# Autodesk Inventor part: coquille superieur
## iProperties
Created: 2002-04
Part Number: coquille superieur
Material: Par défaut
Document SubType Name: Modélisation
Designer: thchene
Control State: 0
Master: False
Checked Out: False
Shininess: 20.0
Angle Display Precision: 2
Document Length Units: 11269
Document Angle Units: 11279
Document Time Units: 11290
Document Mass Units: 11283
Document Length Units Precision: 3
Document Angle Units Precision: 2
Compacted: True
Density: 0.0
Volumn: 0.0
Area: 0.0
PropertySet Name: Model Information
Author: thchene
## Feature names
1. Révolution1 [Revolution]
2. Extrusion6
3. Extrusion3
4. Extrusion4
5. trou avant [Extrusion]
6. Congé1 [Fillet]
7. Perçage trous lame 3 [Hole]
8. Extrusion19
9. Ergot centrage [Extrusion]
10. Extrusion11
11. Extrusion12
12. Congé4 [Fillet]
13. Congé5 [Fillet]
14. Extrusion13
15. Congé6 [Fillet]
16. Congé7 [Fillet]
17. Symétrie1 [Mirror]
18. Extrusion14
19. Congé8 [Fillet]
20. Congé9 [Fillet]
21. Congé11 [Fillet]
22. Perçage3 [Hole]
23. Extrusion15
24. Extrusion16
25. Extrusion17
26. Extrusion18
27. Lissage1
28. Congé12 [Fillet]
